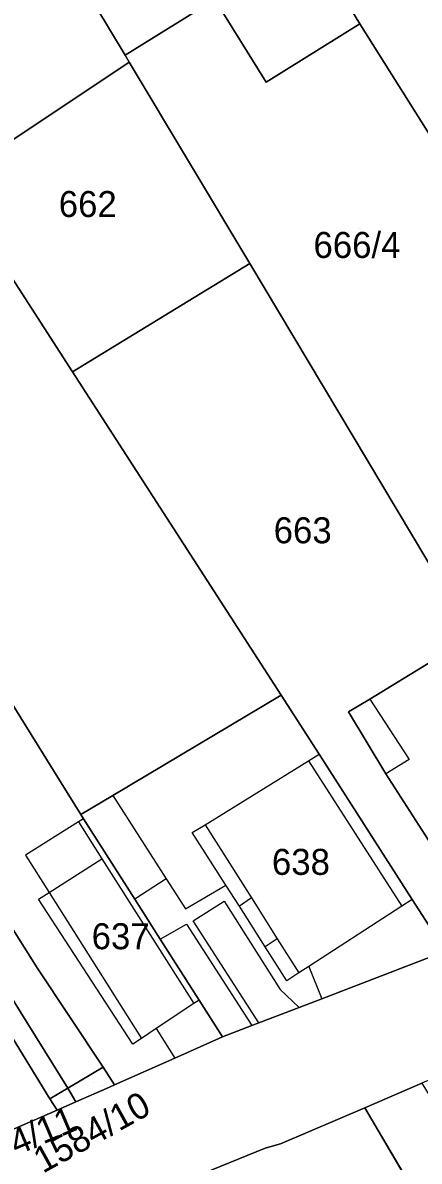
# Model space of a CAD drawing. Extents: x -263943 to -261149, y -1236934 to -1230686.
# Drawn here: x -262535.5 to -262505, y -1235556.7 to -1235469.1 of the extents above; entities that cross this region are included whole.
import ezdxf

# ---------------------------------------------------------------- set-up
doc = ezdxf.new("R2010")
doc.units = 0
for name, color, linetype in [('body_kn', 7, 'Continuous'), ('kladpar_druhypozemkov', 7, 'Continuous'), ('kladpar_hranice', 7, 'Continuous'), ('kladpar_parcelnecisla', 7, 'Continuous'), ('kladpar_plochy', 7, 'Continuous'), ('kladpar_sipky', 7, 'Continuous'), ('zappar_hrandruhpozemk', 7, 'Continuous')]:
    doc.layers.add(name, color=color, linetype=linetype)

msp = doc.modelspace()

# ---------------------------------------------------------------- linework, layer by layer
at = {"layer": 'body_kn'}
for p, q in [((-262509.58, -1235469.21), (-262509.58, -1235469.21)), ((-262509.58, -1235469.21), (-262509.58, -1235469.21)), ((-262527.63, -1235471.62), (-262527.63, -1235471.62)), ((-262527.31, -1235472.16), (-262527.31, -1235472.16)), ((-262516.77, -1235473.71), (-262516.77, -1235473.71)), ((-262518.04, -1235487.66), (-262518.04, -1235487.66)), ((-262531.67, -1235496), (-262531.67, -1235496)), ((-262515.62, -1235520.86), (-262515.62, -1235520.86)), ((-262508.81, -1235521.16), (-262508.81, -1235521.16)), ((-262508.81, -1235521.16), (-262508.81, -1235521.16)), ((-262510.44, -1235522.15), (-262510.44, -1235522.15)), ((-262512.71, -1235525.4), (-262512.71, -1235525.4)), ((-262513.53, -1235525.91), (-262513.53, -1235525.91)), ((-262505.78, -1235525.81), (-262505.78, -1235525.81)), ((-262533.15, -1235526.66), (-262533.15, -1235526.66)), ((-262507.57, -1235526.91), (-262507.57, -1235526.91)), ((-262528.57, -1235528.58), (-262528.57, -1235528.58)), ((-262528.57, -1235528.58), (-262528.57, -1235528.58)), ((-262531.04, -1235530.05), (-262531.04, -1235530.05)), ((-262531.21, -1235530.62), (-262531.21, -1235530.62)), ((-262531.21, -1235530.62), (-262531.21, -1235530.62)), ((-262530.83, -1235530.38), (-262530.83, -1235530.38)), ((-262530.83, -1235530.38), (-262530.83, -1235530.38)), ((-262521.48, -1235530.83), (-262521.48, -1235530.83)), ((-262522.46, -1235531.44), (-262522.46, -1235531.44)), ((-262535.3, -1235533.18), (-262535.3, -1235533.18)), ((-262529.41, -1235533.46), (-262529.41, -1235533.46)), ((-262529.41, -1235533.46), (-262529.41, -1235533.46)), ((-262524.46, -1235534.99), (-262524.46, -1235534.99)), ((-262533.48, -1235536.05), (-262533.48, -1235536.05)), ((-262519.89, -1235535.47), (-262519.89, -1235535.47)), ((-262534.29, -1235536.57), (-262534.29, -1235536.57)), ((-262526.89, -1235536.56), (-262526.89, -1235536.56)), ((-262520.02, -1235536.71), (-262520.02, -1235536.71)), ((-262517.92, -1235536.46), (-262517.92, -1235536.46)), ((-262517.92, -1235536.46), (-262517.92, -1235536.46)), ((-262505.55, -1235536.58), (-262505.55, -1235536.58)), ((-262505.55, -1235536.58), (-262505.55, -1235536.58)), ((-262522.99, -1235537.29), (-262522.99, -1235537.29)), ((-262518.84, -1235537.11), (-262518.84, -1235537.11)), ((-262506.34, -1235537.09), (-262506.34, -1235537.09)), ((-262506.34, -1235537.09), (-262506.34, -1235537.09)), ((-262522.91, -1235538.48), (-262522.91, -1235538.48)), ((-262522.4, -1235538.23), (-262522.4, -1235538.23)), ((-262524.93, -1235539.64), (-262524.93, -1235539.64)), ((-262524.93, -1235539.64), (-262524.93, -1235539.64)), ((-262515.92, -1235539.62), (-262515.92, -1235539.62)), ((-262515.92, -1235539.62), (-262515.92, -1235539.62)), ((-262516.85, -1235540.23), (-262516.85, -1235540.23)), ((-262534.4, -1235541.83), (-262534.4, -1235541.83)), ((-262514.27, -1235542.23), (-262514.27, -1235542.23)), ((-262513.49, -1235541.73), (-262513.49, -1235541.73)), ((-262515.2, -1235542.83), (-262515.2, -1235542.83)), ((-262515.71, -1235543.51), (-262515.71, -1235543.51)), ((-262522.34, -1235544.59), (-262522.34, -1235544.59)), ((-262522.34, -1235544.59), (-262522.34, -1235544.59)), ((-262521.94, -1235544.32), (-262521.94, -1235544.32)), ((-262521.94, -1235544.32), (-262521.94, -1235544.32)), ((-262514.25, -1235544.89), (-262514.25, -1235544.89)), ((-262512.5, -1235544.22), (-262512.5, -1235544.22)), ((-262525.23, -1235546.52), (-262525.23, -1235546.52)), ((-262517.89, -1235546.28), (-262517.89, -1235546.28)), ((-262517.35, -1235546.07), (-262517.35, -1235546.07)), ((-262517.35, -1235546.07), (-262517.35, -1235546.07)), ((-262526.36, -1235547.27), (-262526.36, -1235547.27)), ((-262520.14, -1235547.14), (-262520.14, -1235547.14)), ((-262527.03, -1235547.71), (-262527.03, -1235547.71)), ((-262523.8, -1235548.78), (-262523.8, -1235548.78)), ((-262529.33, -1235549.49), (-262529.33, -1235549.49)), ((-262528.83, -1235551.02), (-262528.83, -1235551.02)), ((-262528.46, -1235550.85), (-262528.46, -1235550.85)), ((-262528.46, -1235550.85), (-262528.46, -1235550.85)), ((-262533.41, -1235551.91), (-262533.41, -1235551.91)), ((-262533.41, -1235551.91), (-262533.41, -1235551.91)), ((-262532.05, -1235551.11), (-262532.05, -1235551.11)), ((-262532.87, -1235552.78), (-262532.87, -1235552.78)), ((-262532.87, -1235552.78), (-262532.87, -1235552.78)), ((-262531.41, -1235552.15), (-262531.41, -1235552.15)), ((-262509.2, -1235552.61), (-262509.2, -1235552.61)), ((-262509.2, -1235552.61), (-262509.2, -1235552.61)), ((-262508.17, -1235554.35), (-262508.17, -1235554.35)), ((-262515.67, -1235555.39), (-262515.67, -1235555.39)), ((-262516.86, -1235555.72), (-262516.86, -1235555.72))]:
    msp.add_line(p, q, dxfattribs=at)
at = {"layer": 'kladpar_druhypozemkov'}
for p, q in [((-262530.43, -1235482.47), (-262530.43, -1235482.47)), ((-262509.6, -1235484.93), (-262509.6, -1235484.93)), ((-262514.25, -1235507.03), (-262514.25, -1235507.03)), ((-262514.06, -1235532.44), (-262514.06, -1235532.44)), ((-262529.12, -1235538.49), (-262529.12, -1235538.49)), ((-262530.09, -1235550.68), (-262530.09, -1235550.68)), ((-262532.59, -1235551.84), (-262532.59, -1235551.84))]:
    msp.add_line(p, q, dxfattribs=at)
at = {"layer": 'kladpar_hranice'}
msp.add_line((-262515.67, -1235555.39), (-262509.2, -1235552.61), dxfattribs=at)
for points in [[(-262509.58, -1235469.21), (-262516.77, -1235473.71), (-262520.69, -1235467.38), (-262515.45, -1235464.23), (-262521.76, -1235453.08), (-262525.31, -1235455.03), (-262536.06, -1235433.39), (-262543.38, -1235424.35), (-262549.68, -1235415.39), (-262544.77, -1235412.33), (-262543.75, -1235413.77), (-262541.48, -1235417.42), (-262538.64, -1235421.97), (-262529.36, -1235436.76), (-262525.35, -1235443.32), (-262520.41, -1235451.38), (-262509.58, -1235469.21)], [(-262522.3, -1235468.31), (-262527.63, -1235471.62), (-262544.51, -1235443.65), (-262536.82, -1235438.69), (-262528.02, -1235456.56), (-262529.63, -1235457.49), (-262522.3, -1235468.31)], [(-262509.58, -1235469.21), (-262520.41, -1235451.38), (-262505.61, -1235441.28), (-262484.57, -1235474.74), (-262500.08, -1235484.3), (-262509.58, -1235469.21)], [(-262539.74, -1235476.14), (-262549.62, -1235460.08), (-262544.29, -1235457.19), (-262549.16, -1235447.8), (-262548.31, -1235447.38), (-262549.33, -1235445.1), (-262545.61, -1235442.13), (-262544.51, -1235443.65), (-262527.63, -1235471.62), (-262527.31, -1235472.16), (-262537.44, -1235478.92), (-262539.74, -1235476.14)], [(-262528.57, -1235528.58), (-262531.04, -1235530.05), (-262533.15, -1235526.66), (-262541.51, -1235513.22), (-262555.52, -1235490.81), (-262571.48, -1235465.29), (-262556.86, -1235456.18), (-262553.69, -1235462.2), (-262553.35, -1235461.97), (-262553.18, -1235461.86), (-262541.16, -1235481.3), (-262531.67, -1235496), (-262515.62, -1235520.86), (-262528.57, -1235528.58)], [(-262541.16, -1235481.3), (-262553.18, -1235461.86), (-262549.62, -1235460.08), (-262539.74, -1235476.14), (-262537.44, -1235478.92), (-262527.31, -1235472.16), (-262518.04, -1235487.66), (-262531.67, -1235496), (-262541.16, -1235481.3)], [(-262490.64, -1235499.3), (-262493.93, -1235501.39), (-262491.68, -1235504.91), (-262494.68, -1235506.81), (-262503.31, -1235512.3), (-262518.04, -1235487.66), (-262527.31, -1235472.16), (-262527.63, -1235471.62), (-262522.3, -1235468.31), (-262520.69, -1235467.38), (-262516.77, -1235473.71), (-262509.58, -1235469.21), (-262500.08, -1235484.3), (-262496.68, -1235489.7), (-262490.64, -1235499.3)], [(-262533.41, -1235551.91), (-262550.56, -1235523.96), (-262575.97, -1235484.12), (-262573.66, -1235482.62), (-262550.61, -1235518.82), (-262551.43, -1235519.32), (-262539.69, -1235538.79), (-262535.71, -1235545.2), (-262532.05, -1235551.11), (-262533.41, -1235551.91)], [(-262554.56, -1235526.49), (-262565.82, -1235508.44), (-262566.15, -1235508.69), (-262570.2, -1235502.25), (-262569.83, -1235502), (-262579.53, -1235486.44), (-262575.97, -1235484.12), (-262550.56, -1235523.96), (-262533.41, -1235551.91), (-262532.87, -1235552.78), (-262537.37, -1235554.74), (-262537.59, -1235554.38), (-262554.56, -1235526.49)], [(-262501.34, -1235516.6), (-262508.81, -1235521.16), (-262510.44, -1235522.15), (-262507.57, -1235526.91), (-262502.5, -1235534.82), (-262499.67, -1235539.23), (-262499.64, -1235539.27), (-262502.99, -1235540.57), (-262505.55, -1235536.58), (-262512.71, -1235525.4), (-262515.62, -1235520.86), (-262531.67, -1235496), (-262518.04, -1235487.66), (-262503.31, -1235512.3), (-262500.9, -1235516.33), (-262501.34, -1235516.6)], [(-262541.51, -1235513.22), (-262533.15, -1235526.66), (-262531.04, -1235530.05), (-262530.83, -1235530.38), (-262526.89, -1235536.56), (-262524.93, -1235539.64), (-262521.94, -1235544.32), (-262520.14, -1235547.14), (-262523.8, -1235548.78), (-262528.46, -1235550.85), (-262529.33, -1235549.49), (-262534.4, -1235541.83), (-262549.38, -1235518.06), (-262541.51, -1235513.22)], [(-262489.79, -1235534.91), (-262499.64, -1235539.27), (-262499.67, -1235539.23), (-262502.5, -1235534.82), (-262507.57, -1235526.91), (-262510.44, -1235522.15), (-262508.81, -1235521.16), (-262501.34, -1235516.6), (-262500.9, -1235516.33), (-262490.12, -1235534.35), (-262489.79, -1235534.91)], [(-262549.38, -1235518.06), (-262534.4, -1235541.83), (-262529.33, -1235549.49), (-262532.05, -1235551.11), (-262535.71, -1235545.2), (-262539.69, -1235538.79), (-262551.43, -1235519.32), (-262550.61, -1235518.82), (-262549.38, -1235518.06)], [(-262537.37, -1235554.74), (-262532.87, -1235552.78), (-262531.41, -1235552.15), (-262528.83, -1235551.02), (-262528.46, -1235550.85), (-262523.8, -1235548.78), (-262520.14, -1235547.14), (-262517.89, -1235546.28), (-262517.35, -1235546.07), (-262514.25, -1235544.89), (-262512.5, -1235544.22), (-262502.99, -1235540.57), (-262499.64, -1235539.27), (-262489.79, -1235534.91), (-262472.53, -1235528.03), (-262455.26, -1235521.99), (-262451.3, -1235520.8), (-262450.59, -1235520.59), (-262444.65, -1235518.81), (-262444.17, -1235518.67)], [(-262502.99, -1235540.57), (-262512.5, -1235544.22), (-262514.25, -1235544.89), (-262517.35, -1235546.07), (-262517.89, -1235546.28), (-262520.14, -1235547.14), (-262521.94, -1235544.32), (-262524.93, -1235539.64), (-262526.89, -1235536.56), (-262530.83, -1235530.38), (-262531.04, -1235530.05), (-262528.57, -1235528.58), (-262515.62, -1235520.86), (-262512.71, -1235525.4), (-262505.55, -1235536.58), (-262502.99, -1235540.57)], [(-262441.86, -1235527.77), (-262449.95, -1235530.54), (-262450.38, -1235530.69), (-262459.13, -1235533.68), (-262460.06, -1235533.09), (-262473.77, -1235540.22), (-262474.96, -1235538.36), (-262475.43, -1235538.55), (-262483.99, -1235541.99), (-262487.66, -1235543.46), (-262487.9, -1235543.07), (-262493.86, -1235545.87), (-262498.17, -1235547.9), (-262503.46, -1235550.14), (-262503.96, -1235550.36), (-262504.81, -1235550.72), (-262509.2, -1235552.61), (-262515.67, -1235555.39), (-262516.86, -1235555.72), (-262521.02, -1235557.42)], [(-262528.46, -1235550.85), (-262528.83, -1235551.02), (-262531.41, -1235552.15), (-262532.05, -1235551.11), (-262529.33, -1235549.49), (-262528.46, -1235550.85)], [(-262485.79, -1235585.63), (-262488.5, -1235587.3), (-262493.08, -1235579.87), (-262494.64, -1235577.23), (-262508.17, -1235554.35), (-262509.2, -1235552.61), (-262504.81, -1235550.72), (-262496.27, -1235564.68), (-262490.09, -1235574.79), (-262487.31, -1235579.33), (-262484.1, -1235584.59)], [(-262532.87, -1235552.78), (-262533.41, -1235551.91), (-262532.05, -1235551.11), (-262531.41, -1235552.15), (-262532.87, -1235552.78)], [(-262509.2, -1235552.61), (-262508.17, -1235554.35), (-262494.64, -1235577.23), (-262493.08, -1235579.87), (-262493.43, -1235580.08), (-262498.42, -1235583.03), (-262493.65, -1235590.8), (-262498.89, -1235594.95), (-262498.9, -1235594.93), (-262507.02, -1235580.87), (-262521.02, -1235557.42), (-262516.86, -1235555.72), (-262515.67, -1235555.39)]]:
    msp.add_lwpolyline(points, dxfattribs=at)
at = {"layer": 'kladpar_plochy'}
for p, q in [((-262509.2, -1235552.61), (-262504.81, -1235550.72)), ((-262515.67, -1235555.39), (-262509.2, -1235552.61)), ((-262508.17, -1235554.35), (-262509.2, -1235552.61)), ((-262509.2, -1235552.61), (-262508.17, -1235554.35)), ((-262494.64, -1235577.23), (-262508.17, -1235554.35)), ((-262508.17, -1235554.35), (-262494.64, -1235577.23)), ((-262516.86, -1235555.72), (-262515.67, -1235555.39)), ((-262521.02, -1235557.42), (-262516.86, -1235555.72))]:
    msp.add_line(p, q, dxfattribs=at)
for points in [[(-262509.58, -1235469.21), (-262516.77, -1235473.71), (-262520.69, -1235467.38), (-262515.45, -1235464.23), (-262521.76, -1235453.08), (-262525.31, -1235455.03), (-262536.06, -1235433.39), (-262543.38, -1235424.35), (-262549.68, -1235415.39), (-262544.77, -1235412.33), (-262543.75, -1235413.77), (-262541.48, -1235417.42), (-262538.64, -1235421.97), (-262529.36, -1235436.76), (-262525.35, -1235443.32), (-262520.41, -1235451.38)], [(-262522.3, -1235468.31), (-262527.63, -1235471.62), (-262544.51, -1235443.65), (-262536.82, -1235438.69), (-262528.02, -1235456.56), (-262529.63, -1235457.49)], [(-262509.58, -1235469.21), (-262520.41, -1235451.38), (-262505.61, -1235441.28), (-262484.57, -1235474.74), (-262500.08, -1235484.3)], [(-262539.74, -1235476.14), (-262549.62, -1235460.08), (-262544.29, -1235457.19), (-262549.16, -1235447.8), (-262548.31, -1235447.38), (-262549.33, -1235445.1), (-262545.61, -1235442.13), (-262544.51, -1235443.65), (-262527.63, -1235471.62), (-262527.31, -1235472.16), (-262537.44, -1235478.92)], [(-262528.57, -1235528.58), (-262531.04, -1235530.05), (-262533.15, -1235526.66), (-262541.51, -1235513.22), (-262555.52, -1235490.81), (-262571.48, -1235465.29), (-262556.86, -1235456.18), (-262553.69, -1235462.2), (-262553.35, -1235461.97), (-262553.18, -1235461.86), (-262541.16, -1235481.3), (-262531.67, -1235496), (-262515.62, -1235520.86)], [(-262541.16, -1235481.3), (-262553.18, -1235461.86), (-262549.62, -1235460.08), (-262539.74, -1235476.14), (-262537.44, -1235478.92), (-262527.31, -1235472.16), (-262518.04, -1235487.66), (-262531.67, -1235496)], [(-262490.64, -1235499.3), (-262493.93, -1235501.39), (-262491.68, -1235504.91), (-262494.68, -1235506.81), (-262503.31, -1235512.3), (-262518.04, -1235487.66), (-262527.31, -1235472.16), (-262527.63, -1235471.62), (-262522.3, -1235468.31), (-262520.69, -1235467.38), (-262516.77, -1235473.71), (-262509.58, -1235469.21), (-262500.08, -1235484.3), (-262496.68, -1235489.7)], [(-262533.41, -1235551.91), (-262550.56, -1235523.96), (-262575.97, -1235484.12), (-262573.66, -1235482.62), (-262550.61, -1235518.82), (-262551.43, -1235519.32), (-262539.69, -1235538.79), (-262535.71, -1235545.2), (-262532.05, -1235551.11)], [(-262554.56, -1235526.49), (-262565.82, -1235508.44), (-262566.15, -1235508.69), (-262570.2, -1235502.25), (-262569.83, -1235502), (-262579.53, -1235486.44), (-262575.97, -1235484.12), (-262550.56, -1235523.96), (-262533.41, -1235551.91), (-262532.87, -1235552.78), (-262537.37, -1235554.74), (-262537.59, -1235554.38)], [(-262501.34, -1235516.6), (-262508.81, -1235521.16), (-262510.44, -1235522.15), (-262507.57, -1235526.91), (-262502.5, -1235534.82), (-262499.67, -1235539.23), (-262499.64, -1235539.27), (-262502.99, -1235540.57), (-262505.55, -1235536.58), (-262512.71, -1235525.4), (-262515.62, -1235520.86), (-262531.67, -1235496), (-262518.04, -1235487.66), (-262503.31, -1235512.3), (-262500.9, -1235516.33)], [(-262541.51, -1235513.22), (-262533.15, -1235526.66), (-262531.04, -1235530.05), (-262530.83, -1235530.38), (-262526.89, -1235536.56), (-262524.93, -1235539.64), (-262521.94, -1235544.32), (-262520.14, -1235547.14), (-262523.8, -1235548.78), (-262528.46, -1235550.85), (-262529.33, -1235549.49), (-262534.4, -1235541.83), (-262549.38, -1235518.06)], [(-262489.79, -1235534.91), (-262499.64, -1235539.27), (-262499.67, -1235539.23), (-262502.5, -1235534.82), (-262507.57, -1235526.91), (-262510.44, -1235522.15), (-262508.81, -1235521.16), (-262501.34, -1235516.6), (-262500.9, -1235516.33), (-262490.12, -1235534.35)], [(-262549.38, -1235518.06), (-262534.4, -1235541.83), (-262529.33, -1235549.49), (-262532.05, -1235551.11), (-262535.71, -1235545.2), (-262539.69, -1235538.79), (-262551.43, -1235519.32), (-262550.61, -1235518.82)], [(-262502.99, -1235540.57), (-262512.5, -1235544.22), (-262514.25, -1235544.89), (-262517.35, -1235546.07), (-262517.89, -1235546.28), (-262520.14, -1235547.14), (-262521.94, -1235544.32), (-262524.93, -1235539.64), (-262526.89, -1235536.56), (-262530.83, -1235530.38), (-262531.04, -1235530.05), (-262528.57, -1235528.58), (-262515.62, -1235520.86), (-262512.71, -1235525.4), (-262505.55, -1235536.58)], [(-262528.46, -1235550.85), (-262528.83, -1235551.02), (-262531.41, -1235552.15), (-262532.05, -1235551.11), (-262529.33, -1235549.49)], [(-262532.87, -1235552.78), (-262533.41, -1235551.91), (-262532.05, -1235551.11), (-262531.41, -1235552.15)]]:
    msp.add_lwpolyline(points, close=True, dxfattribs=at)
for points in [[(-262537.37, -1235554.74), (-262532.87, -1235552.78), (-262531.41, -1235552.15), (-262528.83, -1235551.02), (-262528.46, -1235550.85), (-262523.8, -1235548.78), (-262520.14, -1235547.14), (-262517.89, -1235546.28), (-262517.35, -1235546.07), (-262514.25, -1235544.89), (-262512.5, -1235544.22), (-262502.99, -1235540.57), (-262499.64, -1235539.27), (-262489.79, -1235534.91), (-262472.53, -1235528.03), (-262455.26, -1235521.99), (-262451.3, -1235520.8), (-262450.59, -1235520.59), (-262444.65, -1235518.81), (-262444.17, -1235518.67)], [(-262441.86, -1235527.77), (-262449.95, -1235530.54), (-262450.38, -1235530.69), (-262459.13, -1235533.68), (-262460.06, -1235533.09), (-262473.77, -1235540.22), (-262474.96, -1235538.36), (-262475.43, -1235538.55), (-262483.99, -1235541.99), (-262487.66, -1235543.46), (-262487.9, -1235543.07), (-262493.86, -1235545.87), (-262498.17, -1235547.9), (-262503.46, -1235550.14), (-262503.96, -1235550.36), (-262504.81, -1235550.72), (-262509.2, -1235552.61), (-262515.67, -1235555.39), (-262516.86, -1235555.72), (-262521.02, -1235557.42)]]:
    msp.add_lwpolyline(points, dxfattribs=at)
at = {"layer": 'kladpar_sipky'}
for p, q in [((-262529.4, -1235550.92), (-262529.4, -1235550.92)), ((-262532.52, -1235552.28), (-262532.52, -1235552.28))]:
    msp.add_line(p, q, dxfattribs=at)
at = {"layer": 'zappar_hrandruhpozemk'}
for p, q in [((-262508.81, -1235521.16), (-262505.78, -1235525.81)), ((-262513.53, -1235525.91), (-262512.71, -1235525.4)), ((-262521.48, -1235530.83), (-262513.53, -1235525.91)), ((-262513.53, -1235525.91), (-262506.34, -1235537.09)), ((-262505.78, -1235525.81), (-262507.57, -1235526.91)), ((-262528.57, -1235528.58), (-262524.46, -1235534.99)), ((-262531.21, -1235530.62), (-262529.41, -1235533.46)), ((-262533.48, -1235536.05), (-262529.41, -1235533.46)), ((-262529.41, -1235533.46), (-262522.34, -1235544.59)), ((-262524.46, -1235534.99), (-262526.89, -1235536.56)), ((-262524.46, -1235534.99), (-262522.99, -1235537.29)), ((-262534.29, -1235536.57), (-262533.48, -1235536.05)), ((-262533.48, -1235536.05), (-262526.36, -1235547.27)), ((-262522.99, -1235537.29), (-262519.89, -1235535.47)), ((-262527.03, -1235547.71), (-262534.29, -1235536.57)), ((-262522.4, -1235538.23), (-262520.02, -1235536.71)), ((-262517.92, -1235536.46), (-262518.84, -1235537.11)), ((-262505.55, -1235536.58), (-262506.34, -1235537.09)), ((-262506.34, -1235537.09), (-262513.49, -1235541.73)), ((-262524.93, -1235539.64), (-262522.91, -1235538.48)), ((-262522.91, -1235538.48), (-262517.89, -1235546.28)), ((-262517.35, -1235546.07), (-262522.4, -1235538.23)), ((-262515.92, -1235539.62), (-262516.85, -1235540.23)), ((-262513.49, -1235541.73), (-262512.5, -1235544.22)), ((-262522.34, -1235544.59), (-262525.23, -1235546.52)), ((-262521.94, -1235544.32), (-262522.34, -1235544.59)), ((-262525.23, -1235546.52), (-262523.8, -1235548.78))]:
    msp.add_line(p, q, dxfattribs=at)
for points in [[(-262530.83, -1235530.38), (-262531.21, -1235530.62), (-262535.3, -1235533.18), (-262533.48, -1235536.05)], [(-262513.49, -1235541.73), (-262514.27, -1235542.23), (-262515.2, -1235542.83), (-262516.85, -1235540.23), (-262518.84, -1235537.11), (-262519.89, -1235535.47), (-262522.46, -1235531.44), (-262521.48, -1235530.83)], [(-262521.48, -1235530.83), (-262517.92, -1235536.46), (-262515.92, -1235539.62), (-262514.27, -1235542.23)], [(-262520.02, -1235536.71), (-262515.71, -1235543.51), (-262514.25, -1235544.89)], [(-262525.23, -1235546.52), (-262526.36, -1235547.27), (-262527.03, -1235547.71)]]:
    msp.add_lwpolyline(points, dxfattribs=at)

# ---------------------------------------------------------------- texts
at = {"layer": 'kladpar_parcelnecisla'}
for s, p in [('662', (-262532.736, -1235484.08)), ('666/4', (-262513.139, -1235487.23)), ('663', (-262516.201, -1235509.18)), ('638', (-262516.335, -1235534.69)), ('637', (-262530.204, -1235540.41))]:
    msp.add_text(s, height=2, dxfattribs=at).set_placement(p)
for s, rotation, p in [('1584/10', 29, (-262533.953, -1235557.689)), ('1584/11', 23, (-262540.099, -1235558.046))]:
    msp.add_text(s, height=2, rotation=rotation, dxfattribs=at).set_placement(p)

doc.saveas('drawing.dxf')
